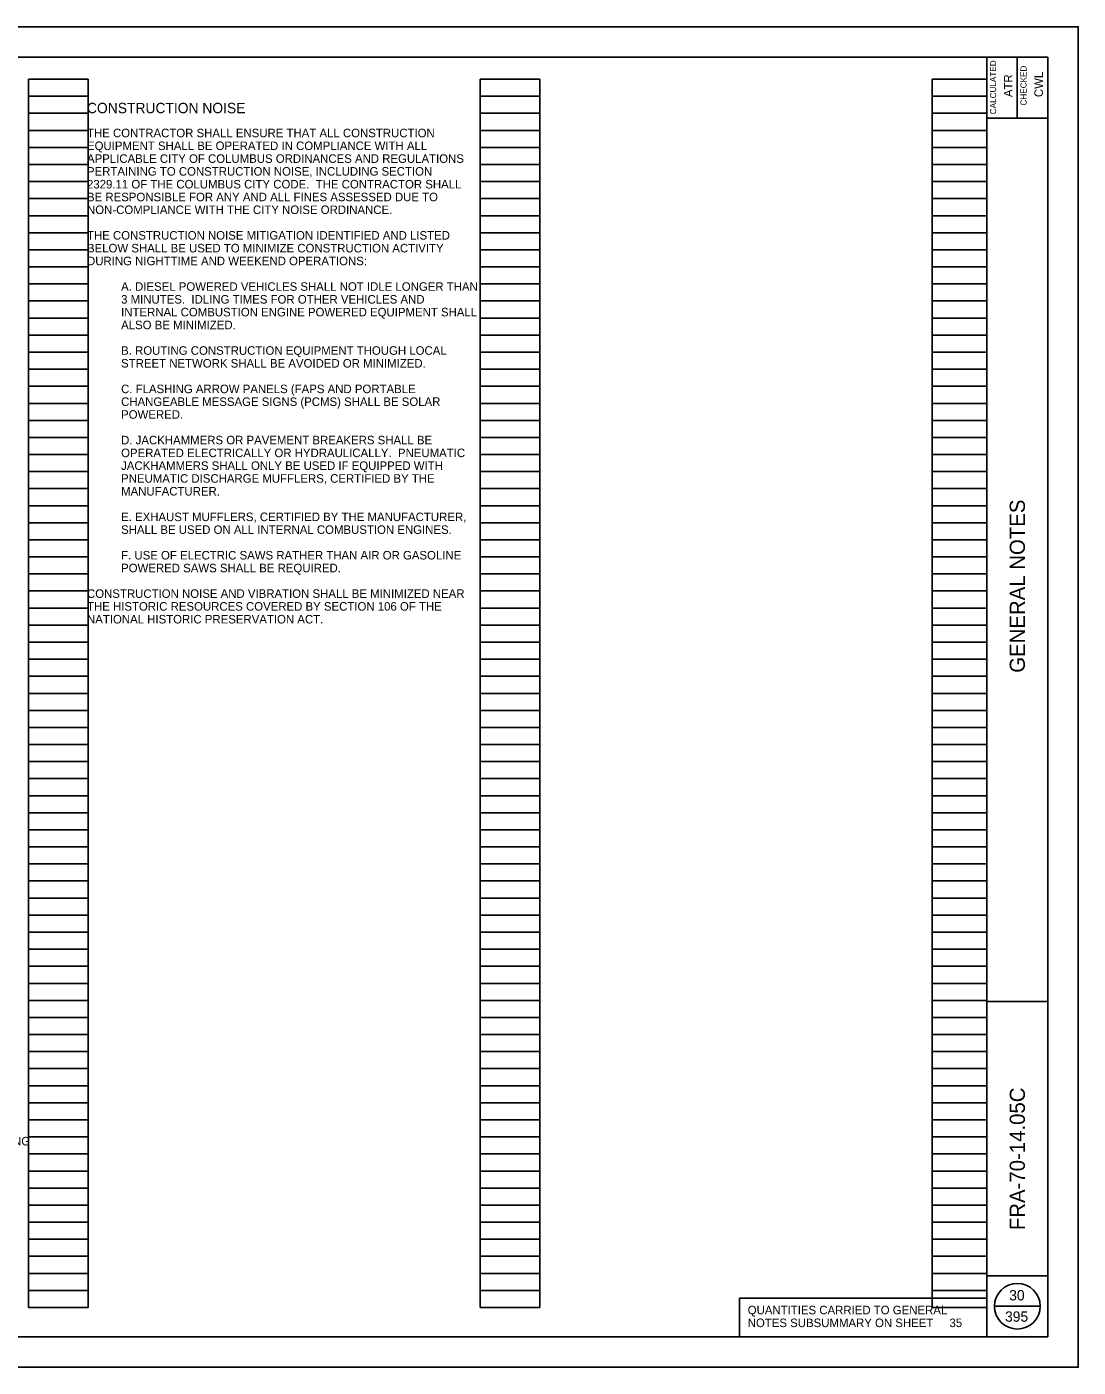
# Model space of a CAD drawing. Extents: x 0 to 34, y 0 to 22.
# Drawn here: x 16.73 to 34, y 0 to 22 of the extents above; entities that cross this region are included whole.
import ezdxf

# ---------------------------------------------------------------- set-up
doc = ezdxf.new("R2010")
doc.units = 0
for name, color, linetype in [('SC_Scratch1', 7, 'Continuous'), ('SH_Border', 7, 'Continuous'), ('SH_Cut_Line', 7, 'Continuous'), ('SH_Data', 7, 'Continuous'), ('SH_Text', 7, 'Continuous'), ('TX_P_1', 7, 'Continuous')]:
    doc.layers.add(name, color=color, linetype=linetype)

msp = doc.modelspace()

# ---------------------------------------------------------------- linework, layer by layer
at = {"layer": 'SC_Scratch1'}
for p, q in [((16.76, 0.98), (16.76, 21.14)), ((16.76, 21.14), (17.74, 21.14)), ((17.74, 0.98), (17.74, 21.14)), ((24.18, 0.98), (24.18, 21.14)), ((24.18, 21.14), (25.16, 21.14)), ((25.16, 0.98), (25.16, 21.14)), ((31.6, 0.98), (31.6, 21.14)), ((31.6, 21.14), (32.5, 21.14)), ((32.5, 0.98), (32.5, 21.14)), ((16.76, 20.86), (17.74, 20.86)), ((24.18, 20.86), (25.16, 20.86)), ((31.6, 20.86), (32.5, 20.86)), ((16.76, 20.58), (17.74, 20.58)), ((24.18, 20.58), (25.16, 20.58)), ((31.6, 20.58), (32.5, 20.58)), ((16.76, 20.3), (17.74, 20.3)), ((24.18, 20.3), (25.16, 20.3)), ((31.6, 20.3), (32.5, 20.3)), ((16.76, 20.02), (17.74, 20.02)), ((24.18, 20.02), (25.16, 20.02)), ((31.6, 20.02), (32.5, 20.02)), ((16.76, 19.74), (17.74, 19.74)), ((24.18, 19.74), (25.16, 19.74)), ((31.6, 19.74), (32.5, 19.74)), ((16.76, 19.46), (17.74, 19.46)), ((24.18, 19.46), (25.16, 19.46)), ((31.6, 19.46), (32.5, 19.46)), ((16.76, 19.18), (17.74, 19.18)), ((24.18, 19.18), (25.16, 19.18)), ((31.6, 19.18), (32.5, 19.18)), ((16.76, 18.9), (17.74, 18.9)), ((24.18, 18.9), (25.16, 18.9)), ((31.6, 18.9), (32.5, 18.9)), ((16.76, 18.62), (17.74, 18.62)), ((24.18, 18.62), (25.16, 18.62)), ((31.6, 18.62), (32.5, 18.62)), ((16.76, 18.34), (17.74, 18.34)), ((24.18, 18.34), (25.16, 18.34)), ((31.6, 18.34), (32.5, 18.34)), ((16.76, 18.06), (17.74, 18.06)), ((24.18, 18.06), (25.16, 18.06)), ((31.6, 18.06), (32.5, 18.06)), ((16.76, 17.78), (17.74, 17.78)), ((24.18, 17.78), (25.16, 17.78)), ((31.6, 17.78), (32.5, 17.78)), ((16.76, 17.5), (17.74, 17.5)), ((24.18, 17.5), (25.16, 17.5)), ((31.6, 17.5), (32.5, 17.5)), ((16.76, 17.22), (17.74, 17.22)), ((24.18, 17.22), (25.16, 17.22)), ((31.6, 17.22), (32.5, 17.22)), ((16.76, 16.94), (17.74, 16.94)), ((24.18, 16.94), (25.16, 16.94)), ((31.6, 16.94), (32.5, 16.94)), ((16.76, 16.66), (17.74, 16.66)), ((24.18, 16.66), (25.16, 16.66)), ((31.6, 16.66), (32.5, 16.66)), ((16.76, 16.38), (17.74, 16.38)), ((24.18, 16.38), (25.16, 16.38)), ((31.6, 16.38), (32.5, 16.38)), ((16.76, 16.1), (17.74, 16.1)), ((24.18, 16.1), (25.16, 16.1)), ((31.6, 16.1), (32.5, 16.1)), ((16.76, 15.82), (17.74, 15.82)), ((24.18, 15.82), (25.16, 15.82)), ((31.6, 15.82), (32.5, 15.82)), ((16.76, 15.54), (17.74, 15.54)), ((24.18, 15.54), (25.16, 15.54)), ((31.6, 15.54), (32.5, 15.54)), ((16.76, 15.26), (17.74, 15.26)), ((24.18, 15.26), (25.16, 15.26)), ((31.6, 15.26), (32.5, 15.26)), ((16.76, 14.98), (17.74, 14.98)), ((24.18, 14.98), (25.16, 14.98)), ((31.6, 14.98), (32.5, 14.98)), ((16.76, 14.7), (17.74, 14.7)), ((24.18, 14.7), (25.16, 14.7)), ((31.6, 14.7), (32.5, 14.7)), ((16.76, 14.42), (17.74, 14.42)), ((24.18, 14.42), (25.16, 14.42)), ((31.6, 14.42), (32.5, 14.42)), ((16.76, 14.14), (17.74, 14.14)), ((24.18, 14.14), (25.16, 14.14)), ((31.6, 14.14), (32.5, 14.14)), ((16.76, 13.86), (17.74, 13.86)), ((24.18, 13.86), (25.16, 13.86)), ((31.6, 13.86), (32.5, 13.86)), ((16.76, 13.58), (17.74, 13.58)), ((24.18, 13.58), (25.16, 13.58)), ((31.6, 13.58), (32.5, 13.58)), ((16.76, 13.3), (17.74, 13.3)), ((24.18, 13.3), (25.16, 13.3)), ((31.6, 13.3), (32.5, 13.3)), ((16.76, 13.02), (17.74, 13.02)), ((24.18, 13.02), (25.16, 13.02)), ((31.6, 13.02), (32.5, 13.02)), ((16.76, 12.74), (17.74, 12.74)), ((24.18, 12.74), (25.16, 12.74)), ((31.6, 12.74), (32.5, 12.74)), ((16.76, 12.46), (17.74, 12.46)), ((24.18, 12.46), (25.16, 12.46)), ((31.6, 12.46), (32.5, 12.46)), ((16.76, 12.18), (17.74, 12.18)), ((24.18, 12.18), (25.16, 12.18)), ((31.6, 12.18), (32.5, 12.18)), ((16.76, 11.9), (17.74, 11.9)), ((24.18, 11.9), (25.16, 11.9)), ((31.6, 11.9), (32.5, 11.9)), ((16.76, 11.62), (17.74, 11.62)), ((24.18, 11.62), (25.16, 11.62)), ((31.6, 11.62), (32.5, 11.62)), ((16.76, 11.34), (17.74, 11.34)), ((24.18, 11.34), (25.16, 11.34)), ((31.6, 11.34), (32.5, 11.34)), ((16.76, 11.06), (17.74, 11.06)), ((24.18, 11.06), (25.16, 11.06)), ((31.6, 11.06), (32.5, 11.06)), ((16.76, 10.78), (17.74, 10.78)), ((24.18, 10.78), (25.16, 10.78)), ((31.6, 10.78), (32.5, 10.78)), ((16.76, 10.5), (17.74, 10.5)), ((24.18, 10.5), (25.16, 10.5)), ((31.6, 10.5), (32.5, 10.5)), ((16.76, 10.22), (17.74, 10.22)), ((24.18, 10.22), (25.16, 10.22)), ((31.6, 10.22), (32.5, 10.22)), ((16.76, 9.94), (17.74, 9.94)), ((24.18, 9.94), (25.16, 9.94)), ((31.6, 9.94), (32.5, 9.94)), ((16.76, 9.66), (17.74, 9.66)), ((24.18, 9.66), (25.16, 9.66)), ((31.6, 9.66), (32.5, 9.66)), ((16.76, 9.38), (17.74, 9.38)), ((24.18, 9.38), (25.16, 9.38)), ((31.6, 9.38), (32.5, 9.38)), ((16.76, 9.1), (17.74, 9.1)), ((24.18, 9.1), (25.16, 9.1)), ((31.6, 9.1), (32.5, 9.1)), ((16.76, 8.82), (17.74, 8.82)), ((24.18, 8.82), (25.16, 8.82)), ((31.6, 8.82), (32.5, 8.82)), ((16.76, 8.54), (17.74, 8.54)), ((24.18, 8.54), (25.16, 8.54)), ((31.6, 8.54), (32.5, 8.54)), ((16.76, 8.26), (17.74, 8.26)), ((24.18, 8.26), (25.16, 8.26)), ((31.6, 8.26), (32.5, 8.26)), ((16.76, 7.98), (17.74, 7.98)), ((24.18, 7.98), (25.16, 7.98)), ((31.6, 7.98), (32.5, 7.98)), ((16.76, 7.7), (17.74, 7.7)), ((24.18, 7.7), (25.16, 7.7)), ((31.6, 7.7), (32.5, 7.7)), ((16.76, 7.42), (17.74, 7.42)), ((24.18, 7.42), (25.16, 7.42)), ((31.6, 7.42), (32.5, 7.42)), ((16.76, 7.14), (17.74, 7.14)), ((24.18, 7.14), (25.16, 7.14)), ((31.6, 7.14), (32.5, 7.14)), ((16.76, 6.86), (17.74, 6.86)), ((24.18, 6.86), (25.16, 6.86)), ((31.6, 6.86), (32.5, 6.86)), ((16.76, 6.58), (17.74, 6.58)), ((24.18, 6.58), (25.16, 6.58)), ((31.6, 6.58), (32.5, 6.58)), ((16.76, 6.3), (17.74, 6.3)), ((24.18, 6.3), (25.16, 6.3)), ((31.6, 6.3), (32.5, 6.3)), ((16.76, 6.02), (17.74, 6.02)), ((24.18, 6.02), (25.16, 6.02)), ((31.6, 6.02), (32.5, 6.02)), ((16.76, 5.74), (17.74, 5.74)), ((24.18, 5.74), (25.16, 5.74)), ((31.6, 5.74), (32.5, 5.74)), ((16.76, 5.46), (17.74, 5.46)), ((24.18, 5.46), (25.16, 5.46)), ((31.6, 5.46), (32.5, 5.46)), ((16.76, 5.18), (17.74, 5.18)), ((24.18, 5.18), (25.16, 5.18)), ((31.6, 5.18), (32.5, 5.18)), ((16.76, 4.9), (17.74, 4.9)), ((24.18, 4.9), (25.16, 4.9)), ((31.6, 4.9), (32.5, 4.9)), ((16.76, 4.62), (17.74, 4.62)), ((24.18, 4.62), (25.16, 4.62)), ((31.6, 4.62), (32.5, 4.62)), ((16.76, 4.34), (17.74, 4.34)), ((24.18, 4.34), (25.16, 4.34)), ((31.6, 4.34), (32.5, 4.34)), ((16.76, 4.06), (17.74, 4.06)), ((24.18, 4.06), (25.16, 4.06)), ((31.6, 4.06), (32.5, 4.06)), ((16.76, 3.78), (17.74, 3.78)), ((24.18, 3.78), (25.16, 3.78)), ((31.6, 3.78), (32.5, 3.78)), ((16.76, 3.5), (17.74, 3.5)), ((24.18, 3.5), (25.16, 3.5)), ((31.6, 3.5), (32.5, 3.5)), ((16.76, 3.22), (17.74, 3.22)), ((24.18, 3.22), (25.16, 3.22)), ((31.6, 3.22), (32.5, 3.22)), ((16.76, 2.94), (17.74, 2.94)), ((24.18, 2.94), (25.16, 2.94)), ((31.6, 2.94), (32.5, 2.94)), ((16.76, 2.66), (17.74, 2.66)), ((24.18, 2.66), (25.16, 2.66)), ((31.6, 2.66), (32.5, 2.66)), ((16.76, 2.38), (17.74, 2.38)), ((24.18, 2.38), (25.16, 2.38)), ((31.6, 2.38), (32.5, 2.38)), ((16.76, 2.1), (17.74, 2.1)), ((24.18, 2.1), (25.16, 2.1)), ((31.6, 2.1), (32.5, 2.1)), ((16.76, 1.82), (17.74, 1.82)), ((24.18, 1.82), (25.16, 1.82)), ((31.6, 1.82), (32.5, 1.82)), ((16.76, 1.54), (17.74, 1.54)), ((24.18, 1.54), (25.16, 1.54)), ((31.6, 1.54), (32.5, 1.54)), ((16.76, 1.26), (17.74, 1.26)), ((24.18, 1.26), (25.16, 1.26)), ((31.6, 1.26), (32.5, 1.26)), ((16.76, 0.98), (17.74, 0.98)), ((24.18, 0.98), (25.16, 0.98)), ((31.6, 0.98), (32.5, 0.98))]:
    msp.add_line(p, q, dxfattribs=at)
at = {"layer": 'SH_Border'}
for p, q in [((32.5, 0.5), (32.5, 21.5)), ((33, 21.5), (33, 20.5)), ((32.5, 20.5), (33.5, 20.5)), ((32.5, 6), (33.5, 6)), ((32.5, 1.5), (33.5, 1.5))]:
    msp.add_line(p, q, dxfattribs=at)
msp.add_lwpolyline([(2, 21.5), (33.5, 21.5), (33.5, 0.5), (2, 0.5)], close=True, dxfattribs=at)
at = {"layer": 'SH_Cut_Line'}
msp.add_lwpolyline([(0, 0), (34, 0), (34, 22), (0, 22)], close=True, dxfattribs=at)
at = {"layer": 'SH_Data'}
msp.add_line((32.625, 1), (33.375, 1), dxfattribs=at)
msp.add_circle((33, 1), 0.375, dxfattribs=at)
at = {"layer": 'TX_P_1'}
msp.add_lwpolyline([(28.437, 1.132), (32.5, 1.132), (32.5, 0.5), (28.437, 0.5)], close=True, dxfattribs=at)

# ---------------------------------------------------------------- texts
at = {"layer": 'SH_Data'}
for s, height, p in [('CALCULATED', 0.1, (32.652, 20.565)), ('CHECKED', 0.1, (33.152, 20.708)), ('ATR', 0.14, (32.92, 20.846)), ('CWL', 0.14, (33.42, 20.846)), ('GENERAL NOTES', 0.25, (33.125, 11.398)), ('FRA-70-14.05C', 0.25, (33.125, 2.249))]:
    msp.add_text(s, height=height, rotation=90, dxfattribs=at).set_placement(p)
for s, p in [('30', (32.867, 1.096)), ('395', (32.799, 0.746))]:
    msp.add_text(s, height=0.17, dxfattribs=at).set_placement(p)
at = {"layer": 'SH_Text'}
for s, p in [('THE CONTRACTOR SHALL ENSURE THAT ALL CONSTRUCTION ', (17.723, 20.187)), ('EQUIPMENT SHALL BE OPERATED IN COMPLIANCE WITH ALL ', (17.723, 19.977)), ('APPLICABLE CITY OF COLUMBUS ORDINANCES AND REGULATIONS ', (17.723, 19.767)), ('PERTAINING TO CONSTRUCTION NOISE, INCLUDING SECTION ', (17.723, 19.557)), ('2329.11 OF THE COLUMBUS CITY CODE.  THE CONTRACTOR SHALL ', (17.723, 19.347)), ('BE RESPONSIBLE FOR ANY AND ALL FINES ASSESSED DUE TO ', (17.723, 19.137)), ('NON-COMPLIANCE WITH THE CITY NOISE ORDINANCE.', (17.723, 18.927)), ('THE CONSTRUCTION NOISE MITIGATION IDENTIFIED AND LISTED ', (17.723, 18.507)), ('BELOW SHALL BE USED TO MINIMIZE CONSTRUCTION ACTIVITY ', (17.723, 18.297)), ('DURING NIGHTTIME AND WEEKEND OPERATIONS:', (17.723, 18.087)), ('A. DIESEL POWERED VEHICLES SHALL NOT IDLE LONGER THAN ', (18.283, 17.667)), ('3 MINUTES.  IDLING TIMES FOR OTHER VEHICLES AND ', (18.283, 17.457)), ('INTERNAL COMBUSTION ENGINE POWERED EQUIPMENT SHALL ', (18.283, 17.247)), ('ALSO BE MINIMIZED.', (18.283, 17.037)), ('B. ROUTING CONSTRUCTION EQUIPMENT THOUGH LOCAL ', (18.283, 16.617)), ('STREET NETWORK SHALL BE AVOIDED OR MINIMIZED.', (18.283, 16.407)), ('C. FLASHING ARROW PANELS (FAPS AND PORTABLE ', (18.283, 15.987)), ('CHANGEABLE MESSAGE SIGNS (PCMS) SHALL BE SOLAR ', (18.283, 15.777)), ('POWERED.', (18.283, 15.567)), ('D. JACKHAMMERS OR PAVEMENT BREAKERS SHALL BE ', (18.283, 15.147)), ('OPERATED ELECTRICALLY OR HYDRAULICALLY.  PNEUMATIC ', (18.283, 14.937)), ('JACKHAMMERS SHALL ONLY BE USED IF EQUIPPED WITH ', (18.283, 14.727)), ('PNEUMATIC DISCHARGE MUFFLERS, CERTIFIED BY THE ', (18.283, 14.517)), ('MANUFACTURER.', (18.283, 14.307)), ('E. EXHAUST MUFFLERS, CERTIFIED BY THE MANUFACTURER, ', (18.283, 13.887)), ('SHALL BE USED ON ALL INTERNAL COMBUSTION ENGINES.', (18.283, 13.677)), ('F. USE OF ELECTRIC SAWS RATHER THAN AIR OR GASOLINE ', (18.283, 13.257)), ('POWERED SAWS SHALL BE REQUIRED.', (18.283, 13.047)), ('CONSTRUCTION NOISE AND VIBRATION SHALL BE MINIMIZED NEAR ', (17.723, 12.627)), ('THE HISTORIC RESOURCES COVERED BY SECTION 106 OF THE ', (17.723, 12.417)), ('NATIONAL HISTORIC PRESERVATION ACT.', (17.723, 12.207)), ('PRE-CONSTRUCTION SURVEY TO THE ENGINEER BEFORE BEGINNING ', (10.32, 3.64))]:
    msp.add_text(s, height=0.14, dxfattribs=at).set_placement(p)
at = {"layer": 'TX_P_1'}
for s, height, p in [('CONSTRUCTION NOISE', 0.17, (17.723, 20.582)), ('QUANTITIES CARRIED TO GENERAL', 0.14, (28.573, 0.868)), ('NOTES SUBSUMMARY ON SHEET', 0.14, (28.573, 0.658)), ('35', 0.14, (31.886, 0.658))]:
    msp.add_text(s, height=height, dxfattribs=at).set_placement(p)

doc.saveas('drawing.dxf')
